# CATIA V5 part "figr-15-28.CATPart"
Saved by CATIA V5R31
Part number: Part1
Bounding box of the stored display mesh (mm): x -61.282 to 61.282, y -26.72 to 26.72, z 0 to 45.75
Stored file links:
  D:\PROJECTS\Project 2021\US EDITION\CATIA V5 6R 2021\Resources\Part Files\c15_catia_v5_6r2021_prt\figr-15-28.CATPart
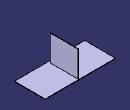
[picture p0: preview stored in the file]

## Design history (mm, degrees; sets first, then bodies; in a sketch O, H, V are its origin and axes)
SheetMetalParameters1: Thickness 0.75, BendRadius 1, KFactor 0.356492 {= log(min(100,max(20*SheetMetalParameters1.BendRadius,SheetMetalParameters1.Thickness)/SheetMetalParameters1.Thickness))/log(100)/2}, ReliefRadialLength 1, ReliefAxialLength 2, MinimumBendRadius 0
Body1 (main body)
  Sketch1 on xy-plane, origin (0, 0, 0), H (1, 0, 0), V (0, 1, 0)
    line L1 (61.282, 26.7197) -> (61.282, -26.7197)
    line L2 (61.282, -26.7197) -> (-61.282, -26.7197)
    line L3 (-61.282, -26.7197) -> (-61.282, 26.7197)
    line L4 (-61.282, 26.7197) -> (61.282, 26.7197)
    vertical: L1 V, L3 V
    horizontal: L2 H, L4 H
    equidistance: L1 L3 O, L2 L4 O
  Wall1: Thickness 0.75, Profile Sketch1
  Sketch2 on face of Wall1, origin (0, 0, 0.75), H (1, 0, 0), V (0, 1, 0)
    line L1 (1.9015, 25.4615) -> (1.9015, -22.9675)
    vertical: L1 V
  d_Extrude1: Extrude_Thickness 0.75, Extrude_Profile Sketch2, Extrude_StartLength 45, Extrude_EndLength 0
